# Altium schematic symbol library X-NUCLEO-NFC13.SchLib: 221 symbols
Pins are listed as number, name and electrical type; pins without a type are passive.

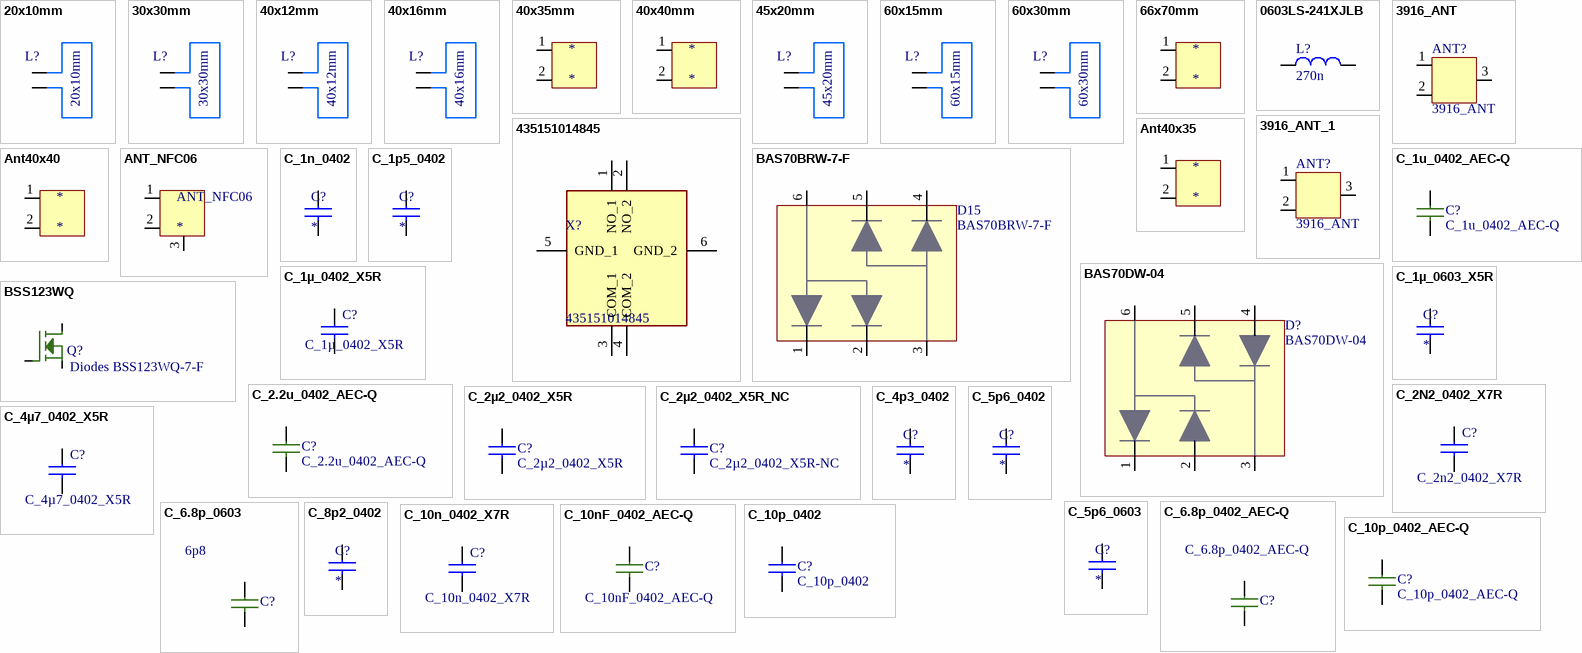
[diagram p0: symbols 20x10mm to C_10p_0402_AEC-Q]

## 20x10mm
designator L?, comment Loop Antenna  (value not drawn)
3turns; 0.2mm width; 0.2mm gap
footprint 20x10mm (3turns; 0.2mm width; 0.2mm gap)
pins: 1, 2

## 30x30mm
designator L?, comment Loop Antenna  (value not drawn)
3turns; 0.3mm width; 0.15mm gap
footprint 30x30mm (2turns; 0.3mm width; 0.15mm gap)
pins: 1, 2

## 40x12mm
designator L?, comment Loop Antenna  (value not drawn)
3turns; 0.3mm width; 0.15mm gap
footprint 40x12mm (3turns; 0.3mm width; 0.15mm gap)
pins: 1, 2

## 40x16mm
designator L?, comment Loop Antenna  (value not drawn)
3turns; 0.3mm width; 0.15mm gap
footprint 40x16mm (3turns; 0.3mm width; 0.15mm gap)
pins: 1, 2

## 40x35mm
designator *  (net tie, no BOM)
4turns;
footprint ANT40x35 (40mm times 35mm)
pins: 1, 2, 3 hidden

## 40x40mm
designator *  (net tie, no BOM)
4turns;
footprint ANT40x40 (40mm times 40mm)
pins: 1, 2, 3 hidden

## 45x20mm
designator L?, comment Loop Antenna  (value not drawn)
3turns; 0.3mm width; 0.15mm gap
footprint 45x20mm (2turns; 0.3mm width; 0.15mm gap)
pins: 1, 2

## 60x15mm
designator L?, comment Loop Antenna  (value not drawn)
3turns; 0.3mm width; 0.15mm gap
footprint 60x15mm (2turns; 0.3mm width; 0.15mm gap)
pins: 1, 2

## 60x30mm
designator L?, comment Loop Antenna  (value not drawn)
2turns; 0.3mm width; 0.15mm gap
footprint 60x30mm (2turns; 0.3mm width; 0.15mm gap)
pins: 1, 2

## 66x70mm
designator *  (net tie, no BOM)
2turns
footprint ST25R_3916DB_66x66mm (66mm x 66mm)
pins: 1, 2

## 0603LS-241XJLB
designator L?, comment 270n
MLJ1608WR27JT000; Manufacturer: TDK; 2nd Source: 0.27 uH 5 % 0.55A 0603
footprint L0603
pins: 1, 2

## 3916_ANT
designator ANT?  (net tie, no BOM)
ST25R3916 DB Ant
footprint ST25R_3916DB__ANTM_42x48mm (42mm x 48mm)
footprint ST25R_3916DB__ANTL_66x66mm (66mm x 66mm)
pins: 1, 2, 3

## 3916_ANT_1
designator ANT?, comment 3916_ANT  (net tie, no BOM)
ST25R300
footprint ST25R300_ANTL_66X66MM (66mm x 66mm)
pins: 1, 2, 3

## 435151014845
designator X?
Tactile Switches WS-TASV Tact Switch; Manufacturer_Name: Wurth Elektronik; Geometry.Height: 1.4mm
footprint 435151014845
pins: 1 NO_1, 2 NO_2, 3 COM_1, 4 COM_2, 5 GND_1, 6 GND_2

## Ant40x35
designator *  (net tie, no BOM)
footprint ANT40x35 (40mm times 35mm)
pins: 1, 2, 3 hidden

## Ant40x40
designator *  (net tie, no BOM)
footprint ANT40x40 (40mm times 40mm)
pins: 1, 2, 3 hidden

## ANT_NFC06
designator ANT_NFC06  (net tie, no BOM)
ANT_NFC06
footprint ANT_NFC08 (40mm times 35mm)
pins: 1, 2, 3

## BAS70BRW-7-F
designator D15
Schottky Diodes & Rectifiers 200MW 70V BRIDGE; Manufacturer: Micro Commercial Components (MCC)
footprint BAS70BRW (SOT363)
pins: 1, 2, 3, 4, 5, 6

## BAS70DW-04
designator D?
Schottky Diodes & Rectifiers 200MW 70V BRIDGE; Manufacturer: Micro Commercial Components (MCC)
footprint BAS70BRW (SOT363)
pins: 1, 2, 3, 4, 5, 6

## BSS123WQ
designator Q?, comment Diodes BSS123WQ-7-F
nCh MOS Fet; Manufacturer: Diodes Incorporated; 2nd Source: no
footprint SOT323
pins: 1 G, 2 S, 3 D

## C_1n_0402
designator C?
1n_COG; Manufacturer: MURATA; Manufacturer Part Number: GRM1555C1H102GA01D; 2nd Source: 1nF ±2% 50V  C0G, NP0 0402
footprint C0402
pins: 1, 2

## C_1p5_0402
designator C?
1p5_COG; Manufacturer: MURATA; Manufacturer Part Number: GRM1555C1H1R5CA01J; 2nd Source: 1,5pF ±0,25pF 50V  C0G, NP0 0603
footprint C0603
pins: 1, 2

## C_1u_0402_AEC-Q
designator C?
1u_X7s; Manufacturer: Murata; Manufacturer Part Number: GRT155R70J105KE01D; 2nd Source: AEC-Q200 10uF ±10% 6.3V 0402
footprint C0402
pins: 1, 2

## C_1µ_0402_X5R
designator C?
1u_X5R; Manufacturer: MURATA; Manufacturer Part Number: GRM155R61C105KA12D; 2nd Source: 0402, 1 µF, 16 V, ± 10%, X5R,
footprint C0402
pins: 1, 2

## C_1µ_0603_X5R
designator C?
1u_X5R; Manufacturer: MURATA; Manufacturer Part Number: GRM188R61C105KA93D; 2nd Source: 0402, 1 µF, 16 V, ± 10%, X5R
footprint C0603
pins: 1, 2

## C_2.2u_0402_AEC-Q
designator C?
2.2u_X7s; Manufacturer: Murata; Manufacturer Part Number: GRT155C70J225KE13; 2nd Source: AEC-Q200 2.2uF ±10% 6.3V 0402
footprint C0402
pins: 1, 2

## C_2N2_0402_X7R
designator C?, comment C_2n2_0402_X7R
2N2_x7R; Manufacturer: AVX; Manufacturer Part Number: 04023C222KAT2A; 2nd Source: 0402, 2.2 nF, 25 V, ± 10%, X7R
footprint C0402
pins: 1, 2

## C_2µ2_0402_X5R
designator C?
2u2_X5R; Manufacturer: MURATA; Manufacturer Part Number: GRM155R60J225ME01D; 2nd Source: 0402, 2.2 µF, 6.3 V, ± 20%, X5R
footprint C0402
pins: 1, 2

## C_2µ2_0402_X5R_NC
designator C?, comment C_2µ2_0402_X5R-NC
2u2_X5R NC; Manufacturer: MURATA; Manufacturer Part Number: GRM155R60J225ME15D NOT FITTED; 2nd Source: 0402, 2.2 µF, 6.3 V, ± 20%, X5R
footprint C0402
pins: 1, 2

## C_4p3_0402
designator C?
4p3_COG; Manufacturer: MURATA; Manufacturer Part Number: GRM0225C1E4R3BA03L; 2nd Source: 0402, 4.3PF 25V, C0G, 0.1pF
footprint C0402
pins: 1, 2

## C_4µ7_0402_X5R
designator C?
4u7_X5R; Manufacturer: TDK; Manufacturer Part Number: C1005X5R0J475K050BC; 2nd Source: 0402, 4.7 µF, 6.3 V, ± 10%, X5R
footprint C0402
pins: 1, 2

## C_5p6_0402
designator C?
5p6_COG; Manufacturer: MURATA; Manufacturer Part Number: GRM1555C1H5R6DA01D; 2nd Source: 5,6pF ±0,5pF 50V  C0G, NP0 0402
footprint C0402
pins: 1, 2

## C_5p6_0603
designator C?
5p6_COG; Manufacturer: MURATA; Manufacturer Part Number: GRM1885C1H5R6CA01D; 2nd Source: 5,6pF ±0,5pF 50V  C0G, NP0 0603
footprint C0603
pins: 1, 2

## C_6.8p_0402_AEC-Q
designator C?
6.8p_COG; Manufacturer: Murta; Manufacturer Part Number: GCM1555C1H6R8BA16D; 2nd Source: AEC-Q200 6.8pF ±0.1pF 100V  C0G 0402
footprint C0402
pins: 1, 2

## C_6.8p_0603
designator C?, comment 6p8
6.8p_COG; Manufacturer: KEMET; Manufacturer Part Number: C0603C689J5GACTU; 2nd Source: 6.8pF 50V  C0G 0603
footprint C0603
pins: 1, 2

## C_8p2_0402
designator C?
8p2_COG; Manufacturer: MURATA; Manufacturer Part Number: GRM1555C1H8R2CA01D; 2nd Source: 0402, 8.2 pF, 50 V, ± 0.25pF, C0G / NP0
footprint C0402
pins: 1, 2

## C_10n_0402_X7R
designator C?
10n_x7R; Manufacturer: AVX; Manufacturer Part Number: 04023C103KAT2A; 2nd Source: 0402, 0.01 µF, 25 V, ± 10%, X7R
footprint C0402
pins: 1, 2

## C_10nF_0402_AEC-Q
designator C?
10n_X7s; Manufacturer: Murata; Manufacturer Part Number: GCM155R71H103KA55J; 2nd Source: AEC-Q200 10nF ±10% 50V 0402
footprint C0402
pins: 1, 2

## C_10p_0402
designator C?
10p_COG; Manufacturer: MURATA; Manufacturer Part Number: GRM1555C1H100GA01D; 2nd Source: 10pF ±2% 50V  C0G, NP0 0402
footprint C0402
pins: 1, 2

## C_10p_0402_AEC-Q
designator C?
10p_COG; Manufacturer: Murta; Manufacturer Part Number: GCM1555C1H100FA16D; 2nd Source: AEC-Q200 10pF ±1% 100V  C0G 0402
footprint C0402
pins: 1, 2

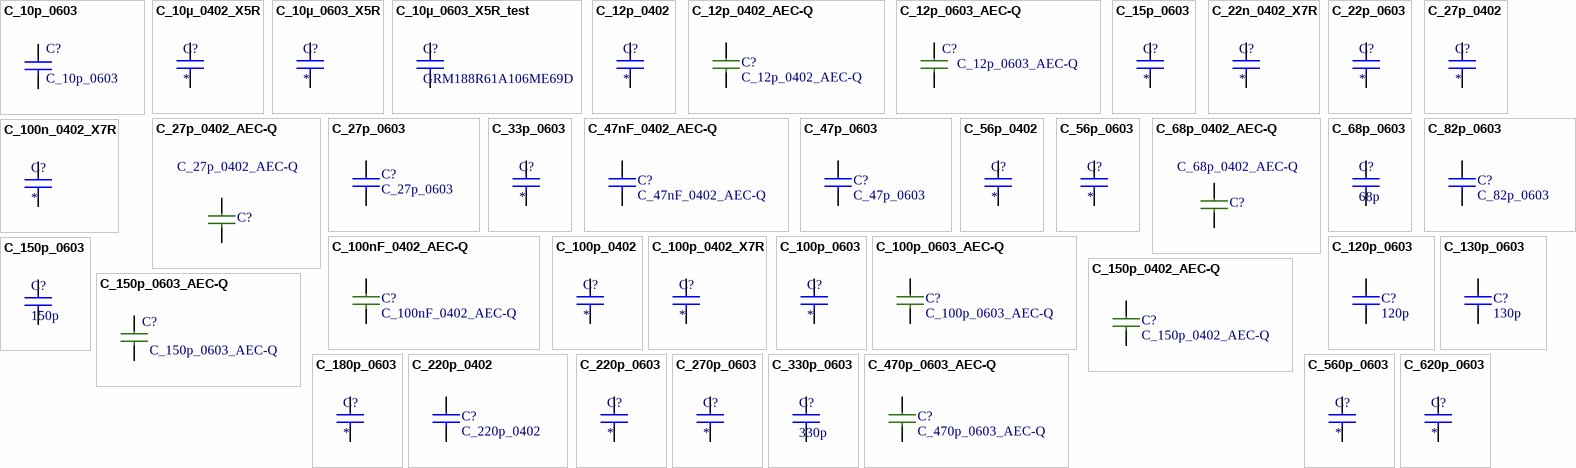
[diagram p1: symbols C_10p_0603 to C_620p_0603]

## C_10p_0603
designator C?
10p_COG; Manufacturer: MULTICOMP; Manufacturer Part Number: MC0603N100F500CT; 2nd Source: 0603, 10pF, 50 V, 1%, C0G / NP0
footprint C0603
pins: 1, 2

## C_10µ_0402_X5R
designator C?
10u_X5R; Manufacturer: muRata; Manufacturer Part Number: GRM155R60G106ME44; 2nd Source: 0402, 10 µF, 6.3 V, ± 10%, X5R
footprint C0402
pins: 1, 2

## C_10µ_0603_X5R
designator C?
10u_X5R; Manufacturer: AVX; Manufacturer Part Number: 06036D106MAT2A; 2nd Source: 0603, 10 µF, 6.3 V, ± 20%, X5R
footprint C0603
pins: 1, 2

## C_10µ_0603_X5R_test
designator C?, comment GRM188R61A106ME69D
10u_X5R
footprint C0603
pins: 1, 2

## C_12p_0402
designator C?
12p_COG; Manufacturer: MURATA; Manufacturer Part Number: GRM1555C1H120GA01D; 2nd Source: 12pF ±2% 50V  C0G, NP0 0402
footprint C0402
pins: 1, 2

## C_12p_0402_AEC-Q
designator C?
12p_COG; Manufacturer: Murta; Manufacturer Part Number: GCM1555C1H120FA16D; 2nd Source: AEC-Q200 12pF ±1% 100V  C0G 0402
footprint C0402
pins: 1, 2

## C_12p_0603_AEC-Q
designator C?
12p_COG; Manufacturer: Murta; Manufacturer Part Number: GCM1885C2A120FA16D; 2nd Source: AEC-Q200 12pF ±1% 100V  C0G 0603
footprint C0603
pins: 1, 2

## C_15p_0603
designator C?
15p_COG; Manufacturer: MULTICOMP; Manufacturer Part Number: MC0603N150J500CT; 2nd Source: 0603, 15pF, 50 V, 1%, C0G / NP0
footprint C0603
pins: 1, 2

## C_22n_0402_X7R
designator C?
22n_x7R; Manufacturer: Murata; Manufacturer Part Number: GRM155R71E223KA61D; 2nd Source: 0402, 0.022 µF, 25 V, ± 10%, X7R
footprint C0402
pins: 1, 2

## C_22p_0603
designator C?
22p_COG; Manufacturer: MURATA; Manufacturer Part Number: GRM1885C1H220FA01D; 2nd Source: 22pF ±2% 50V  C0G, NP0 0603
footprint C0603
pins: 1, 2

## C_27p_0402
designator C?
27p_COG; Manufacturer: MURATA; Manufacturer Part Number: GRM1555C1H270GA01D; 2nd Source: 27pF ±2% 50V  C0G, NP0 0402
footprint C0402
pins: 1, 2

## C_27p_0402_AEC-Q
designator C?
27p_COG; Manufacturer: Murta; Manufacturer Part Number: GCM1555C1H270FA16D; 2nd Source: AEC-Q200 27pF ±1% 100V  C0G 0402
footprint C0402
pins: 1, 2

## C_27p_0603
designator C?
27p_COG; Manufacturer: MURATA; Manufacturer Part Number: GRM1885C1H270FA01D; 2nd Source: 27pF ±2% 50V  C0G, NP0 0603
footprint C0603
pins: 1, 2

## C_33p_0603
designator C?
33p_COGcc; Manufacturer: MURATA; Manufacturer Part Number: GRM1885C1H330FA01D; 2nd Source: 33pF ±2% 50V  C0G, NP0 0603
footprint C0603
pins: 1, 2

## C_47nF_0402_AEC-Q
designator C?
47n_X7s; Manufacturer: Murata; Manufacturer Part Number: GCM155R71E473KA55D; 2nd Source: AEC-Q200 47nF ±10% 10V 0402
footprint C0402
pins: 1, 2

## C_47p_0603
designator C?
47p_COG; Manufacturer: MURATA; Manufacturer Part Number: GRM1885C1H470FA01D; 2nd Source: 47pF ±2% 50V  C0G, NP0 0603
footprint C0603
pins: 1, 2

## C_56p_0402
designator C?
56p_COG; Manufacturer: MURATA; Manufacturer Part Number: GRM1555C1H221GA01D; 2nd Source: 56pF ±2% 50V  C0G, NP0 0402
footprint C0402
pins: 1, 2

## C_56p_0603
designator C?
56p_COG; Manufacturer: MURATA; Manufacturer Part Number: GRM1885C1H560FA01D; 2nd Source: 56pF ±2% 50V  C0G, NP0 0603
footprint C0603
pins: 1, 2

## C_68p_0402_AEC-Q
designator C?
68p_COG; Manufacturer: Murata; Manufacturer Part Number: GCM1555C1H680FA16J; 2nd Source: AEC-Q200 68pF ±1% 50V  C0G 0402
footprint C0402
pins: 1, 2

## C_68p_0603
designator C?, comment 68p
68p_COG; Manufacturer: KEMET; Manufacturer Part Number: C0603C680F1GACTU; 2nd Source: 68pF ±1% 100V  C0G, NP0 0603
footprint C0603
pins: 1, 2

## C_82p_0603
designator C?
82p_COG; Manufacturer: MURATA; Manufacturer Part Number: GRM1885C1H820FA01D; 2nd Source: 82pF ±2% 50V  C0G, NP0 0603
footprint C0603
pins: 1, 2

## C_100n_0402_X7R
designator C?
100n_X7R; Manufacturer: MULTICOMP; Manufacturer Part Number: MC0402X104K100CT; 2nd Source: 0402, 0.1 µF, 10 V, ± 10%, X5R,
footprint C0402
pins: 1, 2

## C_100nF_0402_AEC-Q
designator C?
100n_X7s; Manufacturer: Murata; Manufacturer Part Number: GCM155R71H104KE02J; 2nd Source: AEC-Q200 100nF ±10% 50V 0402
footprint C0402
pins: 1, 2

## C_100p_0402
designator C?
100p_COG; Manufacturer: MURATA; Manufacturer Part Number: GRM1555C1H101GA01D; 2nd Source: 100pF ±2% 50V  C0G, NP0 0402
footprint C0402
pins: 1, 2

## C_100p_0402_X7R
designator C?
100p_X7R; Manufacturer: AVX; Manufacturer Part Number: 0402YC101KAT2A; 2nd Source: 0402, 0.01 µF, 25 V, ± 10%, X7R
footprint C0402
pins: 1, 2

## C_100p_0603
designator C?
100p_COG; Manufacturer: MURATA; Manufacturer Part Number: GRM1885C1H101FA01D; 2nd Source: 100pF ±1% 50V  C0G, NP0 0603
footprint C0603
pins: 1, 2

## C_100p_0603_AEC-Q
designator C?
100p_COG; Manufacturer: Murta; Manufacturer Part Number: GCM1885C2A101FA16D; 2nd Source: AEC-Q200 100pF ±1% 100V  C0G 0603
footprint C0603
pins: 1, 2

## C_120p_0603
designator C?, comment 120p
120p_COG; Manufacturer: KEMET; Manufacturer Part Number: C0603C121J1GACTU; 2nd Source: 120pF ±5% 100V  C0G, NP0 0603
footprint C0603
pins: 1, 2

## C_130p_0603
designator C?, comment 130p
130p_COG; Manufacturer: KEMET; Manufacturer Part Number: C0603C131F5GACTU; 2nd Source: 130pF ±1% 50V  C0G, NP0 0603
footprint C0603
pins: 1, 2

## C_150p_0402_AEC-Q
designator C?
150p_COG; Manufacturer: Murta; Manufacturer Part Number: GCM1555C1H151FA16D; 2nd Source: AEC-Q200 150pF ±1% 50V  C0G 0402
footprint C0402
pins: 1, 2

## C_150p_0603
designator C?, comment 150p
150p_COG; Manufacturer: KEMET; Manufacturer Part Number: C0603C151F5GACTU; 2nd Source: 150pF ±1% 50V  C0G, NP0 0603
footprint C0603
pins: 1, 2

## C_150p_0603_AEC-Q
designator C?
150p_COG; Manufacturer: Murta; Manufacturer Part Number: GCM1885C2A151FA16D; 2nd Source: AEC-Q200 150pF ±1% 100V  C0G 0603
footprint C0603
pins: 1, 2

## C_180p_0603
designator C?
180p_COG; Manufacturer: MURATA; Manufacturer Part Number: GRM1885C1H181GA01D; 2nd Source: 180pF ±2% 50V  C0G, NP0 0603
footprint C0603
pins: 1, 2

## C_220p_0402
designator C?
220p_COG; Manufacturer: MURATA; Manufacturer Part Number: GRM1885C1H221FA01D; 2nd Source: 220pF ±2% 50V  C0G, NP0 0402
footprint C0402
pins: 1, 2

## C_220p_0603
designator C?
220p_COG; Manufacturer: MURATA; Manufacturer Part Number: GRM033R71H221KA12D; 2nd Source: 220pF ±2% 50V  C0G, NP0 0603
footprint C0603
pins: 1, 2

## C_270p_0603
designator C?
270p_COG; Manufacturer: MURATA; Manufacturer Part Number: GRM1885C1H271FA01D; 2nd Source: 270pF ±2% 50V  C0G, NP0 0603
footprint C0603
pins: 1, 2

## C_330p_0603
designator C?, comment 330p
330p_COG; Manufacturer: YAGEO; Manufacturer Part Number: CC0603FRNPO9BN331; 2nd Source: 330pF ±1% 50V  C0G, NP0 0603
footprint C0603
pins: 1, 2

## C_470p_0603_AEC-Q
designator C?
470p_COG; Manufacturer: Murta; Manufacturer Part Number: GCM1885C2A471FA16D; 2nd Source: AEC-Q200 470pF ±1% 100V  C0G 0603
footprint C0603
pins: 1, 2

## C_560p_0603
designator C?
560p_COG; Manufacturer: KEMET; Manufacturer Part Number: C0603C561J3GACTU; 2nd Source: 560pF ±5% 25V  C0G, NP0 0603
footprint C0603
pins: 1, 2

## C_620p_0603
designator C?
620p_COG; Manufacturer: MURATA; Manufacturer Part Number: GCM1885C2A621FA16J; 2nd Source: 620pF ±2% 50V  C0G, NP0 0603
footprint C0603
pins: 1, 2

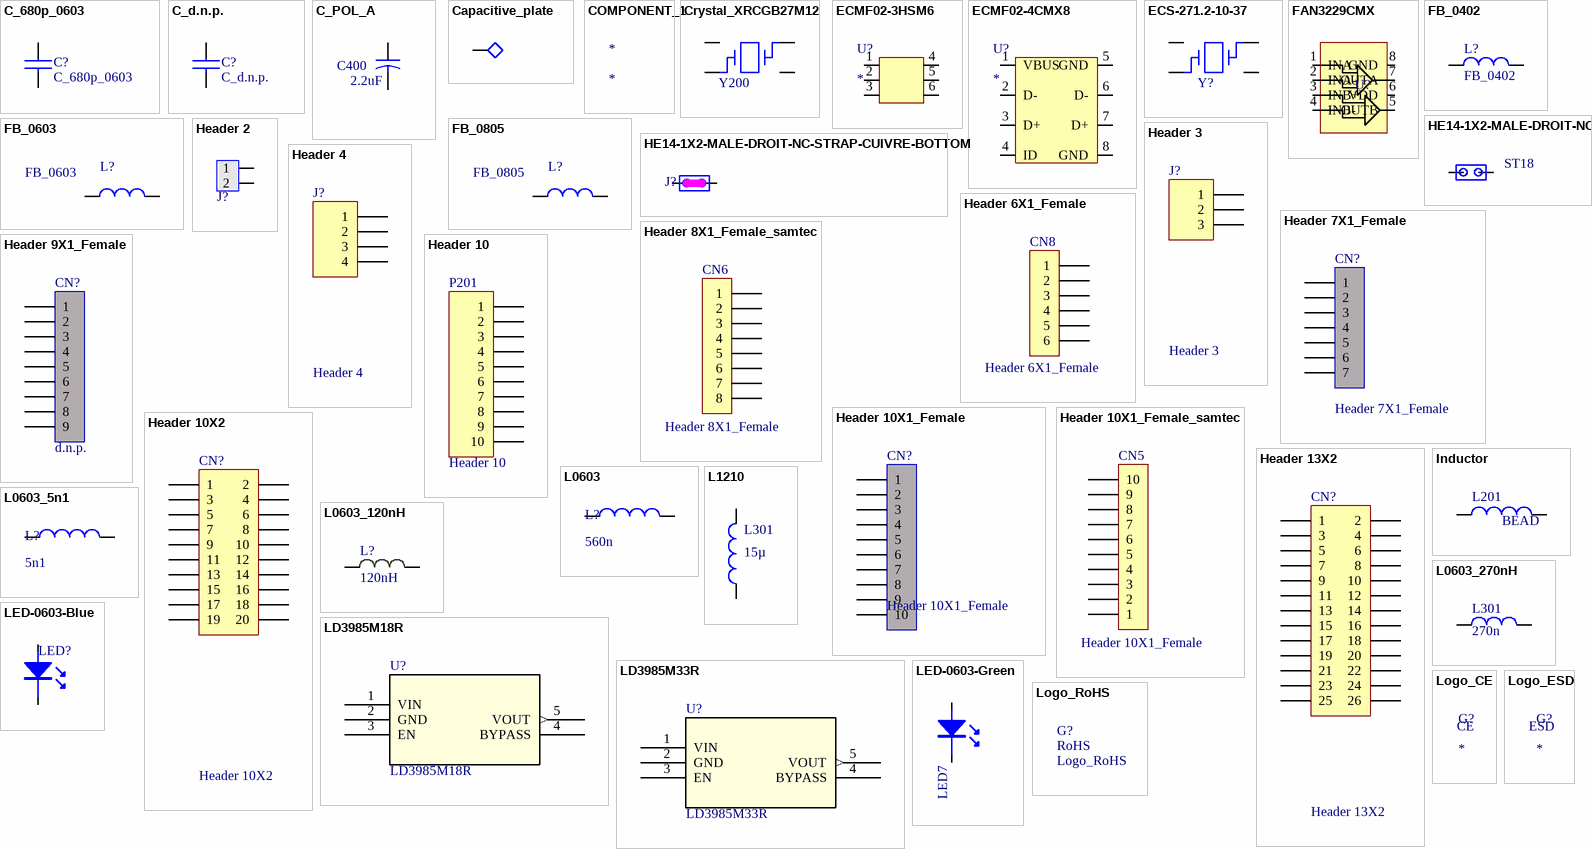
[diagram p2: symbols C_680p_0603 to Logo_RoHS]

## C_680p_0603
designator C?
680p_COG; Manufacturer: MURATA; Manufacturer Part Number: GRM1885C1H681GA01D; 2nd Source: 680pF ±2% 50V  C0G, NP0 0603
footprint C0603
pins: 1, 2

## C_d.n.p.
designator C?
d.n.p.
footprint C0603
footprint C0402
pins: 1, 2

## C_POL_A
designator C400, comment 2.2uF
Manufacturer: Kyocera / AVX; Manufacturer Part Number: TAJA225K010RNJ; Capacitance: 2.2; Voltage Rating: 10; ESR: 7
footprint CP_SMD_A
pins: 1, 2

## Capacitive_plate
designator CP?, comment CS1  (value not drawn)  (no BOM)
Capacitive Sensing
footprint Capacitive_plate
pins: 1

## COMPONENT_1
designator *

## Crystal_XRCGB27M12
designator Y200, comment 27,12MHz Crystal  (value not drawn)
Manufacturer: MURATA; Manufacturer Part Number: XRCGB27M120F3M00R0
footprint XRCGB_F_MN
pins: 1, 2, 3, 4

## ECMF02-3HSM6
designator U?
ECMF02-3HSM6
footprint uQFN-6L (ECMF02-3HSM6)
pins: 1, 2, 3, 4, 5, 6

## ECMF02-4CMX8
designator U?
ECMF02-4CMX8; Manufacturer: STMicroelectronics
footprint uQFN-8L (ECMF02-4CMX8)
pins: 1 VBUS, 2 D-, 3 D+, 4 ID, 5 GND, 6 D-, 7 D+, 8 GND

## ECS-271.2-10-37
designator Y?, comment ECS 27,12MHz Crystal  (value not drawn)
CRYSTAL 27.1200MHZ 10PF SMD; Manufacturer Part Number: ECS-271.2-10-37-CKM-TR
footprint XRCGB_F_MN
pins: 1, 2, 3, 4

## FAN3229CMX
designator U?  (value not drawn)
nCh MOS Fet; Manufacturer: onsemi; 2nd Source: no
footprint FAN3229t (SOIC, 8-Leads, Body 4,90x3,90mm, Pitch 1,27mm, IPC Medium Density)
pins: 1 INA+ (in), 2 INA- (in), 3 INB+ (in), 4 INB- (in), 5 OUTB (out), 6 VDD (power), 7 OUTA (out), 8 GND (power)

## FB_0402
designator L?
Manufacturer: muRata; Manufacturer Part Number: BLM15EG121SH1D; 2nd Source: No
footprint L0402
pins: 1, 2

## FB_0603
designator L?
Manufacturer: MURATA; Manufacturer Part Number: BLM18EG471SN1D
footprint L0603
pins: 1, 2

## FB_0805
designator L?
Manufacturer: TAIYO YUDEN; Manufacturer Part Number: BK2125HS470-T
footprint L0805
pins: 1, 2

## HE14-1X2-MALE-DROIT-NC
designator ST18, comment HE14 2PTS NC  (value not drawn)
CONN HE14 2PTS MALE VERTICAL NOT FITTED; 2nd Source: doublesourcing allowed; PickPlace: No
footprint HE14-1x2-DROIT
pins: 1, 2

## HE14-1X2-MALE-DROIT-NC-STRAP-CUIVRE-BOTTOM
designator J?, comment HE14 2PTS  (value not drawn)  (net tie)
CONN HE14 2PTS MALE VERTICAL NOT FITTED; 2nd Source: doublesourcing allowed
footprint HE14-1x2-DROIT-AVEC-STRAP-CUIVRE-BOTTOM
pins: 1, 2

## Header 2
designator J?, comment d.n.p.  (value not drawn)  (no BOM)
Male Single Row Horizontal 2 pin; 2nd Source: doublesourcing allowed
footprint HDR1X2_slim (Connector; Header; 2 Position)
pins: 1, 2

## Header 3
designator J?
Samtec; Manufacturer Part Number: FTS-103-01-L-S
footprint Header 3X (3 Pin header)
pins: 1, 2, 3

## Header 4
designator J?
Samtec; Manufacturer Part Number: FTS-104-01-L-S
footprint Header 4X (4 Pin header)
pins: 1, 2, 3, 4

## Header 6X1_Female
designator CN8
Header, 6-Pin, Single row,female; Manufacturer: Samtec; Manufacturer Part Number: SSQ-106-03-L-S; Comments: RECEPTACLE, 2.54MM, SINGLE ROW, 6 WAY; 2nd source: doublesourcing allowed; PickPlace: No
footprint SAMTEC-SSQ-1x6-DROIT-STYLE-03
pins: 1, 2, 3, 4, 5, 6

## Header 7X1_Female
designator CN?
d.n.p.; Manufacturer: Samtec; Manufacturer Part Number: SSQ-107-03-L-S; Comments: RECEPTACLE, 2.54MM, SINGLE ROW, 7WAY; 2nd source: doublesourcing allowed
pins: 1, 2, 3, 4, 5, 6, 7

## Header 8X1_Female_samtec
designator CN6, comment Header 8X1_Female
Header, 8-Pin, Single row,female; Manufacturer: Samtec; Manufacturer Part Number: SSQ-108-03-L-S; Comments: RECEPTACLE, 2.54MM, SINGLE ROW, 8WAY; 2nd source: doublesourcing allowed; PickPlace: No
footprint SAMTEC-SSQ-1x8-DROIT-STYLE-03
pins: 1, 2, 3, 4, 5, 6, 7, 8

## Header 9X1_Female
designator CN?, comment d.n.p.  (no BOM)
Manufacturer: Samtec; Manufacturer Part Number: SSQ-107-03-L-S; Comments: RECEPTACLE, 2.54MM, SINGLE ROW, 7WAY; 2nd source: doublesourcing allowed
footprint 1*9P_MALE
pins: 1, 2, 3, 4, 5, 6, 7, 8, 9

## Header 10
designator P201
Samtec; Manufacturer Part Number: FTS-105-01-L-DV
footprint Samtec-Strip5x2
pins: 1, 2, 3, 4, 5, 6, 7, 8, 9, 10

## Header 10X1_Female
designator CN?
TSW-110-08-G-S-RA; Manufacturer: Samtec; Comments: RECEPTACLE, 2.54MM, SINGLE ROW, 7WAY; 2nd source: doublesourcing allowed
pins: 1, 2, 3, 4, 5, 6, 7, 8, 9, 10

## Header 10X1_Female_samtec
designator CN5, comment Header 10X1_Female
Header, 10-Pin, Single row,female; Manufacturer: Samtec; Manufacturer Part Number: SSQ-110-03-L-S; Comments: RECEPTACLE, 2.54MM, SINGLE ROW, 10WAY; 2nd source: doublesourcing allowed; PickPlace: No
footprint SAMTEC-SSQ-1x10-DROIT-STYLE-03
pins: 1, 2, 3, 4, 5, 6, 7, 8, 9, 10

## Header 10X2
designator CN?
Header, 10-Pin, Dual row; Manufacturer: Samtec; Manufacturer Part Number: CES-119-01-T-D; 2nd Source: doublesourcing allowed
signal-integrity model Connector
footprint 2*13P
pins: 1, 2, 3, 4, 5, 6, 7, 8, 9, 10, 11, 12, 13, 14, 15, 16, 17, 18, 19, 20

## Header 13X2
designator CN?
Header, 13-Pin, Dual row; Manufacturer: Würth Elektronik; Manufacturer Part Number: 61202621621; 2nd Source: doublesourcing allowed
signal-integrity model Connector
footprint 2*13P
pins: 1, 2, 3, 4, 5, 6, 7, 8, 9, 10, 11, 12, 13, 14, 15, 16, 17, 18, 19, 20, 21, 22, 23, 24, 25, 26

## Inductor
designator L201, comment BEAD
Inductor
footprint L0603
pins: 1, 2

## L0603
designator L?, comment 560n
COILCRAFT   0603LS-561XGLB   Surface Mount High Frequency Inductor, 0603LS Series, 560 nH,  2%, 0603 [1608 Metric], 525 MHz; Manufacturer Part Number: 0603LS-561XJRC; 2nd Source: No
footprint L0603
pins: 1, 2

## L0603_5n1
designator L?, comment 5n1
COILCRAFT   0603CS-5N1EGTS  Surface Mount High Frequency Inductor, 0603CS Series, 5.1nH,  2%, 0603; Manufacturer Part Number: 0603CS-5N1XJLU; 2nd Source: no; Core Material: Ferrite,Ceramic; Self Resonant Frequency: 525MHz; Inductance: 560nH; Max DC Current: 550mA; DC Resistance (DCR): 440mR; Test Frequency: 7.9MHz; Q Factor: 15
footprint L0603
pins: 1, 2

## L0603_120nH
designator L?, comment 120nH
LQW18CNR27J0ZD; Manufacturer: Murata; Manufacturer Part Number: LQW18CNR12J0ZD; 2nd Source: no
footprint L0603
pins: 1, 2

## L0603_270nH
designator L301, comment 270n
0603LS-271XGRC; Manufacturer: CoilCraft; 2nd Source: no
footprint L0603
pins: 1, 2

## L1210
designator L301, comment 15µ
FIXED IND 15UH 300MA 650 MOHM; Manufacturer: Murata; Manufacturer Part Number: LQH32DN150K53L; 2nd Source: no
footprint L1210
pins: 1, 2

## LD3985M18R
designator U?
1.8V LDO; Manufacturer: STMicroelectronics; 2nd Source: no
footprint LD3985 (SOT23, 5-Leads, Body 2,90x2,80mm, Pitch 0,95mm, IPC Medium Density)
pins: 1 VIN, 2 GND, 3 EN, 4 BYPASS, 5 VOUT (out)

## LD3985M33R
designator U?
3.3V LDO; Manufacturer: STMicroelectronics; 2nd Source: no
footprint LD3985 (SOT23, 5-Leads, Body 2,90x2,80mm, Pitch 0,95mm, IPC Medium Density)
pins: 1 VIN, 2 GND, 3 EN, 4 BYPASS, 5 VOUT (out)

## LED-0603-Blue
designator LED?, comment Blue  (value not drawn)
Manufacturer: Lite-On; Manufacturer Part Number: LTST-C190TBKT
footprint D0603
pins: 1, 2

## LED-0603-Green
designator LED7, comment Green  (value not drawn)
Manufacturer: Lite-On; Manufacturer Part Number: LTST-C190KGKT; PickPlace: Yes
footprint D0603
pins: 1, 2

## Logo_CE
designator G?
footprint Logo_CE (Silk only)

## Logo_ESD
designator G?
footprint Logo_ESD (Silk only)

## Logo_RoHS
designator G?
footprint Logo_RoHS_CHN (Silk only)

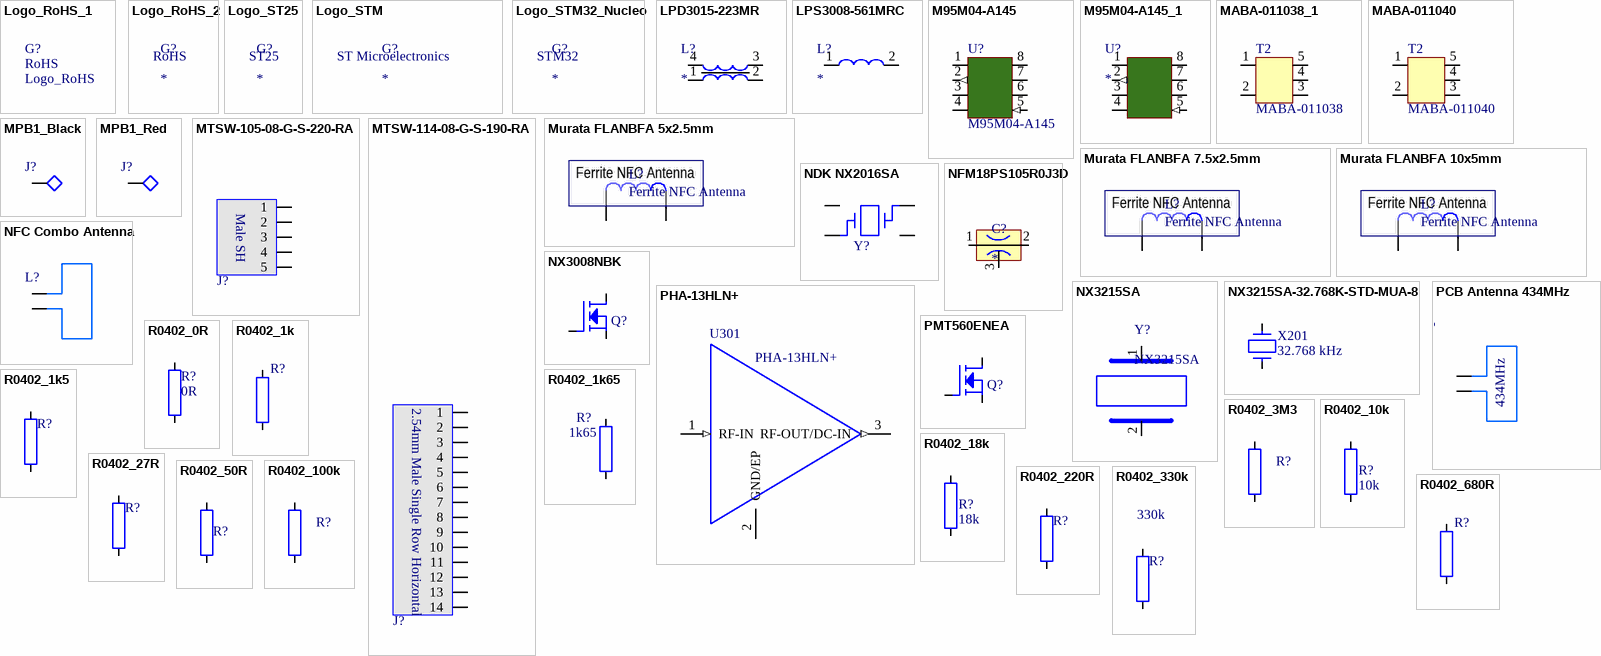
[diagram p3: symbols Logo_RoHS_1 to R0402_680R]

## Logo_RoHS_1
designator G?, comment Logo_RoHS
footprint Logo_RoHS_CHN (Silk only)

## Logo_RoHS_2
designator G?
footprint Logo_RoHS (Silk only)

## Logo_ST25
designator G?
footprint Logo_ST25 (Silk Only)

## Logo_STM
designator G?
footprint Logo_STM (Silk olnly)

## Logo_STM32_Nucleo
designator G?
footprint Logo_STM32 (silk only)

## LPD3015-223MR
designator L?
footprint LPD3015 (LPD3015-223MR_)
pins: 1, 2, 3, 4

## LPS3008-561MRC
designator L?
Manufacturer: CoilCraft; Manufacturer Part Number: LPS3008-561MRC
footprint LPS3008-561MR_
pins: 1, 2

## M95M04-A145
designator U?
footprint TSOP65P640X120-8N (TSOP, 8-Leads, Body 3,00x4,40mm, Pitch 0,65mm, IPC Medium Density)
pins: 1 /CS, 2 MISO (out), 3 /HOLD, 4 VSS (power), 5 MOSI (in), 6, 7 SCLK, 8 VCC (power)

## M95M04-A145_1
designator U?
M95M04-A145
footprint TSOP65P640X120-8N (TSOP, 8-Leads, Body 3,00x4,40mm, Pitch 0,65mm, IPC Medium Density)
pins: 1 /CS, 2 MISO (out), 3 /HOLD, 4 VSS (power), 5 MOSI (in), 6, 7 SCLK, 8 VCC (power)

## MABA-011038_1
designator T2, comment MABA-011038
Manufacturer: MACOM; 2nd Source: no
footprint MABA-011038
pins: 1, 2, 3, 4, 5

## MABA-011040
designator T2
Manufacturer: MACOM; 2nd Source: no
footprint MABA-011038
pins: 1, 2, 3, 4, 5

## MPB1_Black
designator J?, comment MPB1  (value not drawn)
Black MPB1 Power Plug; Manufacturer: HIRSCHMANN TEST AND MEASUREMENT; Manufacturer Part Number: 930224100; 2nd Source: yes
footprint PowerPlug_MPB1SW (Connector; Header; 2 Position)
pins: 1

## MPB1_Red
designator J?, comment MPB1  (value not drawn)
Red MPB1 Power Plug; Manufacturer: HIRSCHMANN TEST AND MEASUREMENT; Manufacturer Part Number: 930224101; 2nd Source: yes
footprint PowerPlug_MPB1R (Connector; Header; 2 Position)
pins: 1

## MTSW-105-08-G-S-220-RA
designator J?, comment Male Single Row Horizontal  (value not drawn)
Headers & Wire Housings Variable Height PCB Header Strips, 0.100" pitch; Manufacturer: Samtec; Manufacturer Part Number: MTSW-105-08-G-S-220-RA; 2nd Source: doublesourcing allowed
footprint MTSW-105-08-G-S-220-RA (5 Pin header 90deg)
pins: 1, 2, 3, 4, 5

## MTSW-114-08-G-S-190-RA
designator J?, comment Male Single Row Horizontal  (value not drawn)
Headers & Wire Housings Variable Height PCB Header Strips, 0.100" pitch; Manufacturer: Samtec; Manufacturer Part Number: MTSW-114-08-G-S-190-RA; 2nd Source: doublesourcing allowed
footprint MTSW-114-08-G-S-190-RA (Footprint not found)
pins: 1, 2, 3, 4, 5, 6, 7, 8, 9, 10, 11, 12, 13, 14

## Murata FLANBFA 5x2.5mm
designator L?, comment Ferrite NFC Antenna
Murata 5x2.5 mm Antenna
footprint FLANBFA 5x2.5MM (Common Footprint for Murata 5 x 2,5 mm Antenna)
pins: 0, 1

## Murata FLANBFA 7.5x2.5mm
designator L?, comment Ferrite NFC Antenna
Murata 7.5x2.5mm Antenna
footprint FLANBFA 7.5x2.5MM (Common Footprint for Murata 7,5 x 2,5 mm Antenna)
pins: 0, 1

## Murata FLANBFA 10x5mm
designator L?, comment Ferrite NFC Antenna
Murata 10x5mm Antenna
footprint FLANBFA 10x5mm (Common Footprint for Murata 10x5 mm Antenna)
pins: 0, 1

## NDK NX2016SA
designator Y?, comment NDK 27,12MHz Crystal  (value not drawn)
NDK NX2016SA 27.12MHz; Manufacturer: MURATA; Manufacturer Part Number: NX2016SA STD-CZS-5 27.12MHz; 2nd Source: Murata XRCGB27M120F3M00R0
footprint XRCGB_F_MN
pins: 1, 2, 3, 4

## NFC Combo Antenna
designator L?, comment Loop Antenna  (value not drawn)
2turns; 0.3mm width; 0.15mm gap
footprint ST25R_3916DB_combo (70mm x 70mm)
pins: 1, 2

## NFM18PS105R0J3D
designator C?
Manufacturer: MURATA; Manufacturer Part Number: NFM18PS105R0J3D
footprint NFM18
pins: 1, 2, 3

## NX3008NBK
designator Q?  (value not drawn)
nCh MOS Fet - NX3008NBK
footprint SOT23
pins: 1 G, 2 S, 3 D

## NX3215SA
designator Y?
32.768kHz; Manufacturer: NDK; Manufacturer Part Number: NX3215SA-32.768K-STD-MUA-8
footprint NX3215SA (NX3215SA-32.768K-STD-MUA-8)
pins: 1, 2

## NX3215SA-32.768K-STD-MUA-8
designator X201, comment 32.768 kHz
Crystal 32kHz; Manufacturer Part Number: NX3215SA-32.768K-STD-MUA-8; Manufacturer: NDK
footprint NX3215SA (NX3215SA-32.768K-STD-MUA-8)
pins: 1, 2
2 alternate drawings of the same symbol

## PCB Antenna 434MHz
designator L?, comment 434MHz PCB Antenna  (net tie, no BOM)
PCB Antenna 434 MHz Reference Design
footprint 434MHz RD PCB Antenna (434MHz Reference PCB Antenna)
pins: 1, 2

## PHA-13HLN+
designator U301
Manufacturer: Mini-Circuits
footprint SOT89-150P410X160-3N (SOT89, 3-Leads, Body 4,49x2,44mm, Pitch 1,50mm, Lead Span 4,1mm, IPC Medium Density)
pins: 1 RF-IN (in), 2 GND/EP, 3 RF-OUT/DC-IN (out)

## PMT560ENEA
designator Q?  (value not drawn)
nCh MOS Fet; Manufacturer Part Number: PMT560ENEAX; Manufacturer: NEXPERIA; 2nd Source: no
footprint SOT23
pins: 1 G, 2 S, 3 D

## R0402_0R
designator R?, comment 0R
0R, 0402; Manufacturer: VISHAY; Manufacturer Part Number: CRCW04020000ZSTD; 2nd Source: 0 ohm, 50 V, 0402, >62.5 mW
footprint R0402
pins: 1, 2

## R0402_1k
designator R?, comment 1k  (value not drawn)
1k, 0402; Manufacturer: Panasonic; Manufacturer Part Number: ERJ2GEJ102X; 2nd Source: 1 kohm, 50 V, 0402, >100 mW, ± 5%
footprint R0402
pins: 1, 2

## R0402_1k5
designator R?, comment 1k5  (value not drawn)
1k5, 0402; Manufacturer: Stackpole Electronics Inc; Manufacturer Part Number: RMCF0402FT1K00; 2nd Source: 1.5 kohm, 50 V, 0402, >100 mW, ± 1%
footprint R0402
pins: 1, 2

## R0402_1k65
designator R?, comment 1k65
1k65, 0402; Manufacturer: MULTICOMP; Manufacturer Part Number: MC00625W040211K65; 2nd Source: 1.65 kohm, 50 V, 0402, >62.5 mW, ± 1%
footprint R0402
pins: 1, 2

## R0402_3M3
designator R?, comment 3M3  (value not drawn)
3M3, 0402; Manufacturer: YAGO; Manufacturer Part Number: RC0402FR-073M3L; 2nd Source: 3.3 Mohm, 50 V, 0402, >62.5 mW, ± 1%
footprint R0402
pins: 1, 2

## R0402_10k
designator R?, comment 10k
10k, 0402; Manufacturer: MULTICOMP; Manufacturer Part Number: MC00625W0402110K; 2nd Source: 10 kohm, 50 V, 0402, >62.5 mW, ± 1%
footprint R0402
pins: 1, 2

## R0402_18k
designator R?, comment 18k
18k, 0402; Manufacturer: MULTICOMP; Manufacturer Part Number: MCWR04X1802FTL; 2nd Source: 18 kohm, 50 V, 0402, >62.5 mW, ± 1%
footprint R0402
pins: 1, 2

## R0402_27R
designator R?, comment 27R  (value not drawn)
27R, 0402; Manufacturer: MULTICOMP; Manufacturer Part Number: MC00625W0402127R; 2nd Source: 27ohm, 50 V, 0402, >62.5 mW, ± 1%
footprint R0402
pins: 1, 2

## R0402_50R
designator R?, comment 50R  (value not drawn)
50R, 0402; Manufacturer: MULTICOMP; Manufacturer Part Number: MCMR04X49R9FTL; 2nd Source: 49.9 ohm, 50 V, 0402, >62.5 mW, ± 1%
footprint R0402
pins: 1, 2

## R0402_100k
designator R?, comment 100k  (value not drawn)
100k, 0402; Manufacturer: YAGO; Manufacturer Part Number: RC0402FR-10100KL; 2nd Source: 100 kohm, 50 V, 0402, >62.5 mW, ± 1%
footprint R0402
pins: 1, 2

## R0402_220R
designator R?, comment 220R  (value not drawn)
220R, 0402; Manufacturer: Yageo; Manufacturer Part Number: RC0402JR-07220RL; 2nd Source: 220 Ohm ±5% 0.063W, 1/16W Chip Resistor 0402
footprint R0402
pins: 1, 2

## R0402_330k
designator R?, comment 330k
330k, 0402; Manufacturer: VISHAY; Manufacturer Part Number: CRCW0402330KFKED; 2nd Source: 330 kohm, 50 V, 0402, >62.5 mW, ± 1%
footprint R0402
pins: 1, 2

## R0402_680R
designator R?, comment 680R  (value not drawn)
680R, 0402; Manufacturer: Yageo; Manufacturer Part Number: RC0402JR-07680RL; 2nd Source: 680 Ohm ±5% 0.063W, 1/16W Chip Resistor 0402
footprint R0402
pins: 1, 2

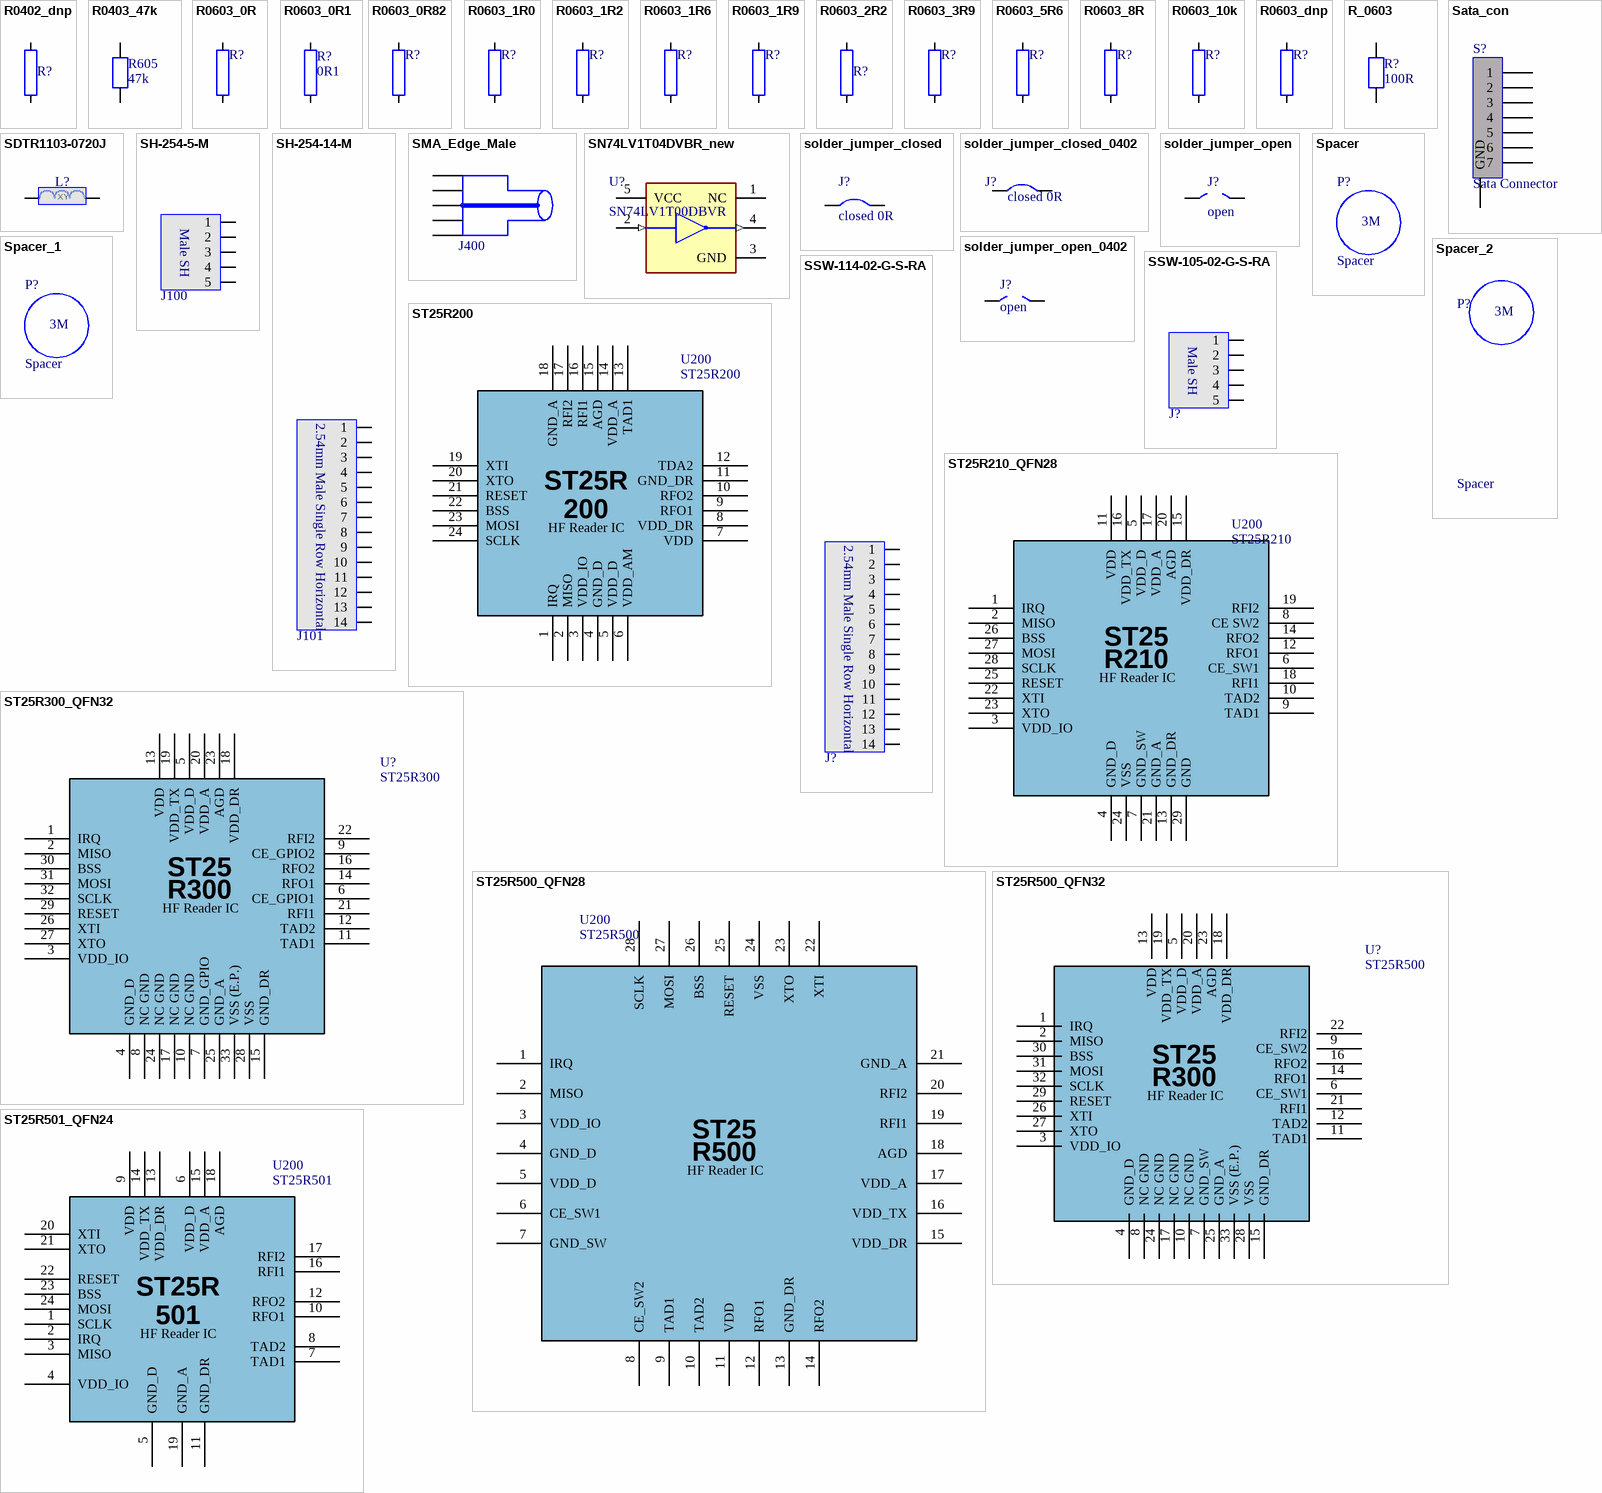
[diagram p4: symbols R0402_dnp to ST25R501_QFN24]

## R0402_dnp
designator R?, comment d.n.p.  (value not drawn)
d.n.p., 0402
footprint R0402
pins: 1, 2

## R0403_47k
designator R605, comment 47k
Manufacturer 1: VISHAY; Manufacturer Part Number: CRCW040247K0FKED; 2nd Source: 47k 0402 1% 62.5mW
footprint R0402
footprint R0603-ss
pins: 1, 2

## R0603_0R
designator R?, comment 0R  (value not drawn)
0R, 0603; Manufacturer: Yageo; Manufacturer Part Number: RC0603FR-070RL; 2nd Source: 0 Ohm ±5% 0.1W, 1/10W Chip Resistor 0603
footprint R0603
pins: 1, 2

## R0603_0R1
designator R?, comment 0R1
0R1, 0603; Manufacturer: MULTICOMP; Manufacturer Part Number: MC00625W040210R; 2nd Source: 0 ohm, 50 V, 0402, >62.5 mW
footprint R0603
pins: 1, 2

## R0603_0R82
designator R?, comment 0R82  (value not drawn)
0R82, 0603; Manufacturer: Panasonic; Manufacturer Part Number: ERJ3BQFR82V; 2nd Source: 0.82 Ohm ±1% 0.33W, 1/3W Chip Resistor 0603
footprint R0603
pins: 1, 2

## R0603_1R0
designator R?, comment 1R0  (value not drawn)
1R0, 0603; Manufacturer: Panasonic; Manufacturer Part Number: ERJ-3RQF1R0V; 2nd Source: 1 Ohm ±1% 0.333W, 1/3W Chip Resistor 0603
footprint R0603
pins: 1, 2

## R0603_1R2
designator R?, comment 1R2  (value not drawn)
1R2, 0603; Manufacturer: Vishay Dale; Manufacturer Part Number: CRCW06031R20FKEA; 2nd Source: 1.2 Ohm ±1% 0.1W, 1/10W Chip Resistor 0603
footprint R0603
pins: 1, 2

## R0603_1R6
designator R?, comment 1R6  (value not drawn)
1R6, 0603; Manufacturer: Vishay Dale; Manufacturer Part Number: CRCW06031R60FKEAHP; 2nd Source: 1.6 Ohm ±1% 0.1W, 1/10W Chip Resistor 0603
footprint R0603
pins: 1, 2

## R0603_1R9
designator R?, comment 1R9  (value not drawn)
1R9, 0603; Manufacturer: Vishay Dale; Manufacturer Part Number: CRCW06031R96FKEA; 2nd Source: 1.96 Ohm ±1% 0.1W, 1/10W Chip Resistor 0603
footprint R0603
pins: 1, 2

## R0603_2R2
designator R?, comment 2R2  (value not drawn)
2R2, 0603; Manufacturer: Vishay Dale; Manufacturer Part Number: CRCW06032R20FKEA; 2nd Source: 2.2 Ohm ±1% 0.1W, 1/10W Chip Resistor 0603
footprint R0603
pins: 1, 2

## R0603_3R9
designator R?, comment 3R9  (value not drawn)
3R9, 0603; Manufacturer: Panasonic; Manufacturer Part Number: ERJ-3GEYJ3R9V; 2nd Source: 3.9 Ohm ±5% 0.1W, 1/10W Chip Resistor 0603
footprint R0603
pins: 1, 2

## R0603_5R6
designator R?, comment 3R9  (value not drawn)
5R6, 0603; Manufacturer: Yageo; Manufacturer Part Number: RC0603FR-075R62L; 2nd Source: 5.6 Ohm ±5% 0.1W, 1/10W Chip Resistor 0603
footprint R0603
pins: 1, 2

## R0603_8R
designator R?, comment 8R  (value not drawn)
8R, 0603; Manufacturer: Yageo; Manufacturer Part Number: 311-18GRTR-ND; 2nd Source: 8 Ohm ±5% 0.1W, 1/10W Chip Resistor 0603
footprint R0603
pins: 1, 2

## R0603_10k
designator R?, comment 10k  (value not drawn)
10k, 0603; Manufacturer: Vishay Dale; Manufacturer Part Number: CRCW060310K0FKTA; 2nd Source: 10 kOhm ±1% 0.1W, 1/10W Chip Resistor 0603
footprint R0603
pins: 1, 2

## R0603_dnp
designator R?, comment dnp  (value not drawn)
dnp, 0603; 2nd Source: d.n.p., 1/10W Chip Resistor 0603
footprint R0603
pins: 1, 2

## R_0603
designator R?, comment 100R
2nd Source: 100R 0402
footprint R0402
footprint R0603-ss
pins: 1, 2

## Sata_con
designator S?, comment Sata Connector
CONN SATA HEADER 7POS SLD PCB; Manufacturer: Molex; Manufacturer Part Number: 0471554001; 2nd source: doublesourcing allowed
footprint Sata Con Molex
pins: 1, 2, 3, 4, 5, 6, 7, 8 GND

## SDTR1103-0720J
designator L?, comment Premo Horizontal Single Axis 125kHz coil  (value not drawn)
footprint SDTR1103 (Premo 125kHz Horizontal Transponder Antenna)
pins: 0, 1

## SH-254-5-M
designator J100, comment Male Single Row Horizontal  (value not drawn)
Male Single Row Horizontal 5 pin; Manufacturer: Samtec; Manufacturer Part Number: TSM-105-01-L-SH; 2nd Source: doublesourcing allowed
footprint Male_SH-254-05 (SMT 2,54mm Single Row Horizontal)
pins: 0 1, 1 2, 2 3, 3 4, 4 5

## SH-254-14-M
designator J101, comment Male Single Row Horizontal  (value not drawn)
Male Single Row Horizontal 14 pin; Manufacturer: Samtec; Manufacturer Part Number: TSM-114-01-L-SH; 2nd Source: doublesourcing allowed
footprint Male_SH-254-14 (SMT 2,54mm Single Row Horizontal)
pins: 0 1, 1 2, 2 3, 3 4, 4 5, 5 6, 6 7, 7 8, 8 9, 9 10, 10 11, 11 12, 12 13, 13 14

## SMA_Edge_Male
designator J400  (value not drawn)
SMA END LAUNCH PLG RCP .062 PC; Manufacturer: Amphenol Connex; Manufacturer Part Number: 132366-10; Body Plating: Gold; Body Material: Brass; Dielectric Material: PTFE; Connector Type: SMA,Receptacle,Male Pin; Max Frequency: 18GHz; Impedance: 50R
footprint Amphenol Connex (132366-10)
pins: 1, 2, 2, 2, 2

## SN74LV1T04DVBR_new
designator U?, comment SN74LV1T00DBVR
Übersetzungsspannungs-Pegel SGL PwrSupply 2-inpt Pos NAND gate; Manufacturer: TI
footprint SOT-23-5
pins: 1 NC, 2 A (in), 3 GND (power), 4 Y (out), 5 VCC (power)

## solder_jumper_closed
designator J?, comment closed 0R  (net tie)
0R; Manufacturer: Multicomp; Manufacturer Part Number: MC00625W040210R
footprint JP2_SMD_closed
pins: 1, 2

## solder_jumper_closed_0402
designator J?, comment closed 0R  (net tie)
0R; Manufacturer: Multicomp; Manufacturer Part Number: MC00625W040210R
footprint JP2_SMD_closed_0402
pins: 1, 2

## solder_jumper_open
designator J?, comment open  (no BOM)
footprint JP2_SMD_open
pins: 1, 2

## solder_jumper_open_0402
designator J?, comment open  (net tie, no BOM)
footprint JP2_SMD_open_0402
pins: 1, 2

## Spacer
designator P?
Samtec; Manufacturer: 3M; Manufacturer Part Number: SJ5303TRANS; 2nd Source: doublesourcing allowed
footprint spacer (spacer d5mmx4mm)

## Spacer_1
designator P?, comment Spacer
Samtec; Manufacturer: 3M; Manufacturer Part Number: SJ5303TRANS; 2nd Source: doublesourcing allowed
footprint SPACER_NEW (spacer d5mmx4mm)

## Spacer_2
designator P?, comment Spacer
Samtec; Manufacturer: 3M; Manufacturer Part Number: SJ5303TRANS; 2nd Source: doublesourcing allowed
footprint SPACER_NEW (spacer d5mmx4mm)

## SSW-105-02-G-S-RA
designator J?, comment Female Single Row Horizontal  (value not drawn)
Female Single Row Horizontal 5 pin; Manufacturer: Samtec; Manufacturer Part Number: SSW-105-02-G-S-RA; 2nd Source: doublesourcing allowed
footprint SSW-105-02-G-S-RA (5 Pin header 90deg)
pins: 1, 2, 3, 4, 5

## SSW-114-02-G-S-RA
designator J?, comment Female Single Row Horizontal  (value not drawn)
Female Single Row Horizontal 14 pin; Manufacturer: Samtec; Manufacturer Part Number: SSW-114-02-G-S-RA; 2nd Source: doublesourcing allowed
footprint SSW-114-02-G-S-RA (14 Pin header 90deg)
pins: 1, 2, 3, 4, 5, 6, 7, 8, 9, 10, 11, 12, 13, 14

## ST25R200
designator U200
HF Reader IC; Manufacturer: STMicroelectronics; Manufacturer Part Number: ST25R3916-AQFMCT-ND
footprint ST25R200 QFN (QFN, 24-Leads, Body 4.00x4.00mm, Pitch 0.50mm, Thermal Pad 2.65x2.65mm, IPC Medium Density)
pins: 1 IRQ, 2 MISO, 3 VDD_IO, 4 GND_D, 5 VDD_D, 6 VDD_AM, 7 VDD, 8 VDD_DR, 9 RFO1, 10 RFO2, 11 GND_DR, 12 TDA2, 13 TAD1, 14 VDD_A, 15 AGD, 16 RFI1, 17 RFI2, 18 GND_A, 19 XTI, 20 XTO, 21 RESET, 22 BSS, 23 MOSI, 24 SCLK, 25 VSS (power)

## ST25R210_QFN28
designator U200, comment ST25R210
HF Reader IC QFN28; Manufacturer: STMicroelectronics
footprint ST25R210_QFN_28 (QFN, 28-Leads, Body 3,95x3,95mm, Pitch 0,40mm, Thermal Pad 2,50x2,50mm, IPC Medium Density)
pins: 1 IRQ, 2 MISO, 3 VDD_IO, 4 GND_D, 5 VDD_D, 6 CE_SW1, 7 GND_SW, 8 CE SW2, 9 TAD1, 10 TAD2, 11 VDD, 12 RFO1, 13 GND_DR, 14 RFO2, 15 VDD_DR, 16 VDD_TX, 17 VDD_A, 18 RFI1, 19 RFI2, 20 AGD, 21 GND_A, 22 XTI, 23 XTO, 24 VSS, 25 RESET, 26 BSS, 27 MOSI, 28 SCLK, 29 GND

## ST25R300_QFN32
designator U?, comment ST25R300
HF Reader IC QFN32; Manufacturer: ST
footprint ST25R300-QFN32_5X5_0.5 (Footprint not found)
pins: 1 IRQ, 2 MISO, 3 VDD_IO, 4 GND_D, 5 VDD_D, 6 CE_GPIO1, 7 GND_GPIO, 8 NC GND, 9 CE_GPIO2, 10 NC GND, 11 TAD1, 12 TAD2, 13 VDD, 14 RFO1, 15 GND_DR, 16 RFO2, 17 NC GND, 18 VDD_DR, 19 VDD_TX, 20 VDD_A, 21 RFI1, 22 RFI2, 23 AGD, 24 NC GND, 25 GND_A, 26 XTI, 27 XTO, 28 VSS, 29 RESET, 30 BSS, 31 MOSI, 32 SCLK, 33 VSS (E.P.)

## ST25R500_QFN28
designator U200, comment ST25R500
HF Reader IC QFN28; Manufacturer: STMicroelectronics; Manufacturer Part Number: ST25R3916-AQFMCT-ND
footprint ST25R3916-QFN32_5X5_0.5
pins: 1 IRQ, 2 MISO, 3 VDD_IO, 4 GND_D, 5 VDD_D, 6 CE_SW1, 7 GND_SW, 8 CE_SW2, 9 TAD1, 10 TAD2, 11 VDD, 12 RFO1, 13 GND_DR, 14 RFO2, 15 VDD_DR, 16 VDD_TX, 17 VDD_A, 18 AGD, 19 RFI1, 20 RFI2, 21 GND_A, 22 XTI, 23 XTO, 24 VSS, 25 RESET, 26 BSS, 27 MOSI, 28 SCLK

## ST25R500_QFN32
designator U?, comment ST25R500
HF Reader IC QFN32; Manufacturer: STMicroelectronics; Manufacturer Part Number: ST25R3916-AQFMCT-ND
footprint ST25R3916-QFN32_5X5_0.5
pins: 1 IRQ, 2 MISO, 3 VDD_IO, 4 GND_D, 5 VDD_D, 6 CE_SW1, 7 GND_SW, 8 NC GND, 9 CE_SW2, 10 NC GND, 11 TAD1, 12 TAD2, 13 VDD, 14 RFO1, 15 GND_DR, 16 RFO2, 17 NC GND, 18 VDD_DR, 19 VDD_TX, 20 VDD_A, 21 RFI1, 22 RFI2, 23 AGD, 24 NC GND, 25 GND_A, 26 XTI, 27 XTO, 28 VSS, 29 RESET, 30 BSS, 31 MOSI, 32 SCLK, 33 VSS (E.P.)

## ST25R501_QFN24
designator U200, comment ST25R501
HF Reader IC QFN24; Manufacturer: STMicroelectronics; Manufacturer Part Number: ST25R3916-AQFMCT-ND
footprint ST25R200 QFN (QFN, 24-Leads, Body 4.00x4.00mm, Pitch 0.50mm, Thermal Pad 2.65x2.65mm, IPC Medium Density)
pins: 1 SCLK, 2 IRQ, 3 MISO, 4 VDD_IO, 5 GND_D, 6 VDD_D, 7 TAD1, 8 TAD2, 9 VDD, 10 RFO1, 11 GND_DR, 12 RFO2, 13 VDD_DR, 14 VDD_TX, 15 VDD_A, 16 RFI1, 17 RFI2, 18 AGD, 19 GND_A, 20 XTI, 21 XTO, 22 RESET, 23 BSS, 24 MOSI, 25 VSS (power)

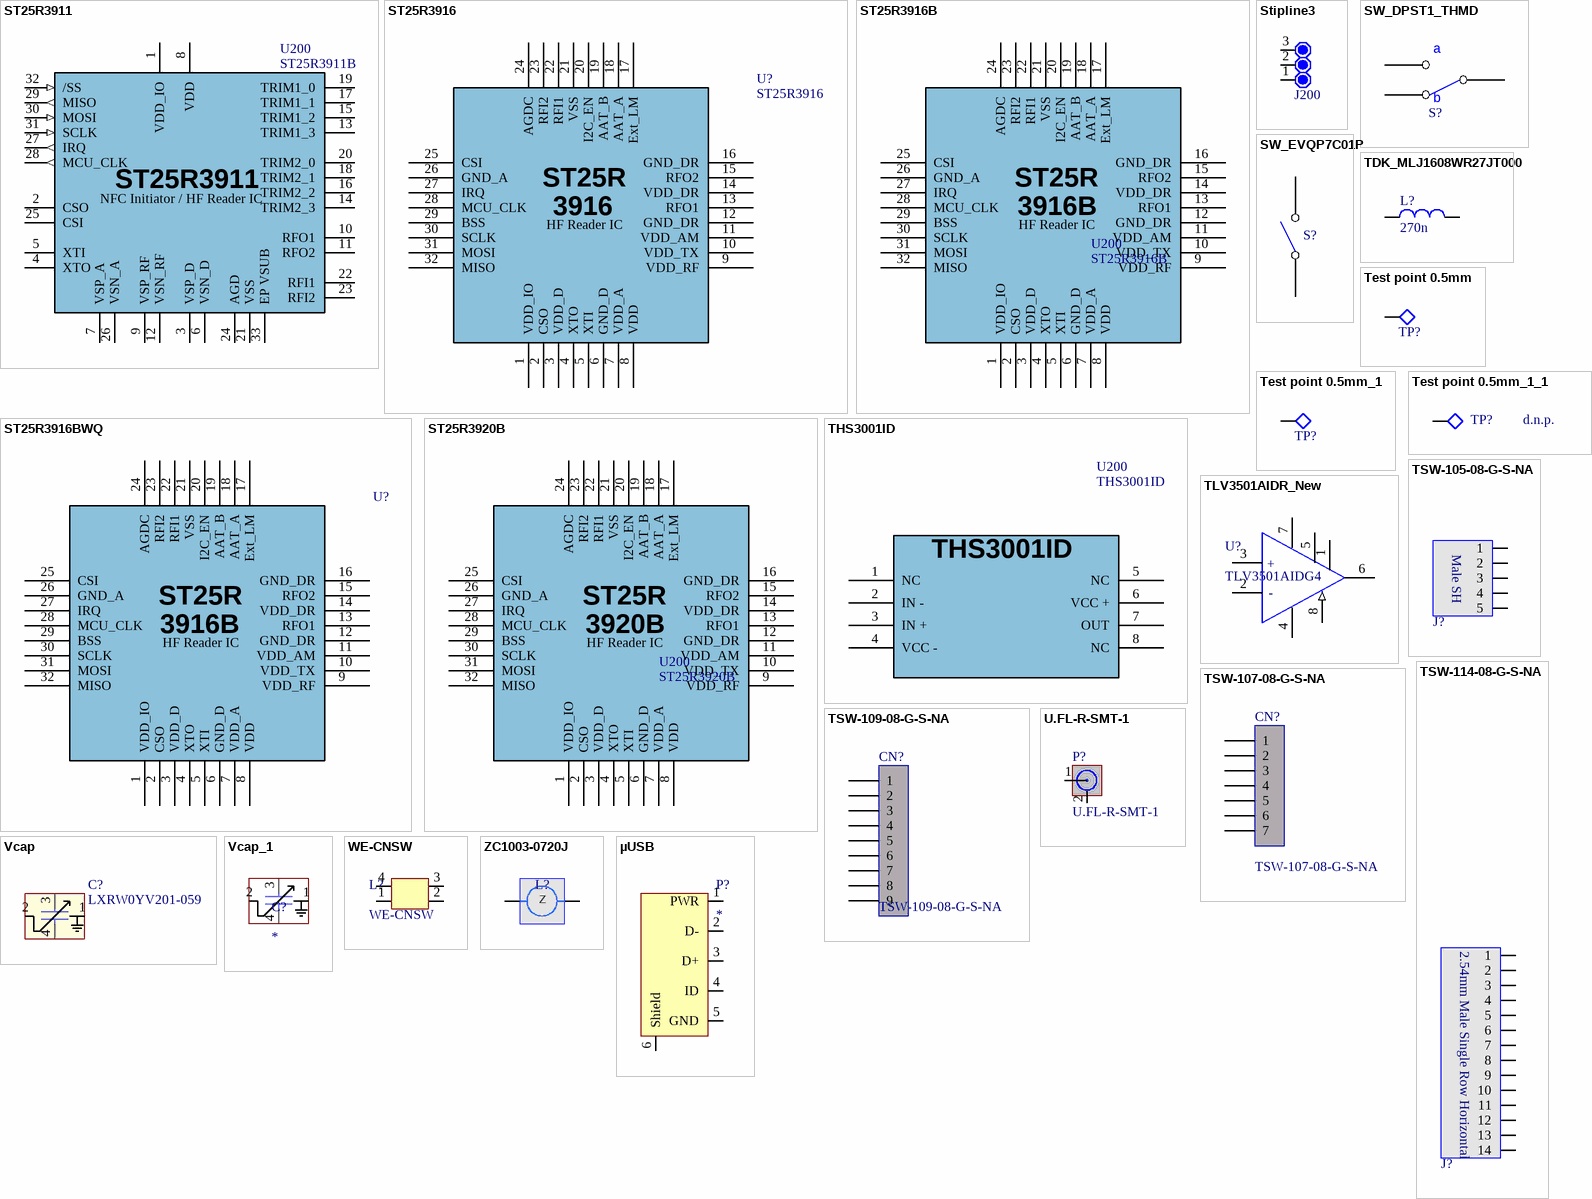
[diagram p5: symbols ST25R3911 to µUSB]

## ST25R3911
designator U200, comment ST25R3911B
NFC Initiator / HF Reader IC; Manufacturer: STMicroelectronics; Manufacturer Part Number: ST25R3911B-AQFMCT-ND
footprint ST25R3911B-QFN32_5X5_0.5
pins: 1 VDD_IO (power), 2 CSO, 3 VSP_D, 4 XTO, 5 XTI, 6 VSN_D (power), 7 VSP_A, 8 VDD (power), 9 VSP_RF, 10 RFO1, 11 RFO2, 12 VSN_RF (power), 13 TRIM1_3, 14 TRIM2_3, 15 TRIM1_2, 16 TRIM2_2, 17 TRIM1_1, 18 TRIM2_1, 19 TRIM1_0, 20 TRIM2_0, 21 VSS (power), 22 RFI1, 23 RFI2, 24 AGD, 25 CSI, 26 VSN_A (power), 27 IRQ (out), 28 MCU_CLK (out), 29 MISO (out), 30 MOSI (in), 31 SCLK (in), 32 /SS (in), 33 EP VSUB

## ST25R3916
designator U?
NFC Initiator / HF Reader IC; Manufacturer: STMicroelectronics; Manufacturer Part Number: ST25R3916-AQFMCT-ND
footprint ST25R3916-QFN32_5X5_0.5
pins: 1 VDD_IO, 2 CSO, 3 VDD_D, 4 XTO, 5 XTI, 6 GND_D, 7 VDD_A, 8 VDD, 9 VDD_RF, 10 VDD_TX, 11 VDD_AM, 12 GND_DR, 13 RFO1, 14 VDD_DR, 15 RFO2, 16 GND_DR, 17 Ext_LM, 18 AAT_A, 19 AAT_B, 20 I2C_EN, 21 VSS, 22 RFI1, 23 RFI2, 24 AGDC, 25 CSI, 26 GND_A, 27 IRQ, 28 MCU_CLK, 29 BSS, 30 SCLK, 31 MOSI, 32 MISO, 33 VSS (power)

## ST25R3916B
designator U200
NFC Initiator / HF Reader IC; Manufacturer: STMicroelectronics; Manufacturer Part Number: ST25R3916-AQFMCT-ND
footprint ST25R3916-QFN32_5X5_0.5
pins: 1 VDD_IO, 2 CSO, 3 VDD_D, 4 XTO, 5 XTI, 6 GND_D, 7 VDD_A, 8 VDD, 9 VDD_RF, 10 VDD_TX, 11 VDD_AM, 12 GND_DR, 13 RFO1, 14 VDD_DR, 15 RFO2, 16 GND_DR, 17 Ext_LM, 18 AAT_A, 19 AAT_B, 20 I2C_EN, 21 VSS, 22 RFI1, 23 RFI2, 24 AGDC, 25 CSI, 26 GND_A, 27 IRQ, 28 MCU_CLK, 29 BSS, 30 SCLK, 31 MOSI, 32 MISO, 33 VSS (power)

## ST25R3916BWQ
designator U?, comment ST25R3916B  (value not drawn)
NFC Initiator / HF Reader IC; Manufacturer: STMicroelectronics; Manufacturer Part Number: ST25R3916-BQW
footprint ST25R3916-QFN32_5X5_0.5
pins: 1 VDD_IO, 2 CSO, 3 VDD_D, 4 XTO, 5 XTI, 6 GND_D, 7 VDD_A, 8 VDD, 9 VDD_RF, 10 VDD_TX, 11 VDD_AM, 12 GND_DR, 13 RFO1, 14 VDD_DR, 15 RFO2, 16 GND_DR, 17 Ext_LM, 18 AAT_A, 19 AAT_B, 20 I2C_EN, 21 VSS, 22 RFI1, 23 RFI2, 24 AGDC, 25 CSI, 26 GND_A, 27 IRQ, 28 MCU_CLK, 29 BSS, 30 SCLK, 31 MOSI, 32 MISO, 33 VSS (power)

## ST25R3920B
designator U200
NFC Initiator / HF Reader IC; Manufacturer: STMicroelectronics; Manufacturer Part Number: ST25R3920B-AQWT
footprint ST25R3916-QFN32_5X5_0.5
pins: 1 VDD_IO, 2 CSO, 3 VDD_D, 4 XTO, 5 XTI, 6 GND_D, 7 VDD_A, 8 VDD, 9 VDD_RF, 10 VDD_TX, 11 VDD_AM, 12 GND_DR, 13 RFO1, 14 VDD_DR, 15 RFO2, 16 GND_DR, 17 Ext_LM, 18 AAT_A, 19 AAT_B, 20 I2C_EN, 21 VSS, 22 RFI1, 23 RFI2, 24 AGDC, 25 CSI, 26 GND_A, 27 IRQ, 28 MCU_CLK, 29 BSS, 30 SCLK, 31 MOSI, 32 MISO, 33 VSS (power)

## Stipline3
designator J200  (value not drawn)
footprint JP3_SMD
pins: 1, 2, 3

## SW_DPST1_THMD
designator S?, comment PCM12SMTR  (value not drawn)
Manufacturer: C & K COMPONENTS
footprint SW_PCM12SMTR
3D model Switch_slide_pcm12smtr (PCB3D Model)
pins: 1, 2, 3

## SW_EVQP7C01P
designator S?, comment EVQP7C01P  (value not drawn)
Manufacturer: Panasonic
footprint SW_EVQP7C01P
3D model Switch_slide_pcm12smtr (PCB3D Model)
pins: 1, 2

## TDK_MLJ1608WR27JT000
designator L?, comment 270n
MLJ1608WR27JT000; Manufacturer: TDK; 2nd Source: 0.27 uH 5 % 0.55A 0603
footprint L0603
pins: 1, 2

## Test point 0.5mm
designator TP?  (value not drawn)  (no BOM)
Part Number: Test point 0.5mm
footprint TP_0.5 (Test Point 0.5mm)
pins: 1 0

## Test point 0.5mm_1
designator TP?, comment d.n.p.  (value not drawn)  (no BOM)
Part Number: Test point 0.5mm
footprint 1*1P_MALE
pins: 1 0

## Test point 0.5mm_1_1
designator TP?, comment d.n.p.  (no BOM)
Part Number: Test point 0.5mm
footprint TP_0.5 (Test Point 0.5mm)
footprint 1*1P_MALE round
footprint TP_1mm
pins: 1 0

## THS3001ID
designator U200
footprint THS3001ID SOIC (D) (SOIC, 8-Leads, Body 3,90x3,90mm, Pitch 1,27mm, IPC Medium Density)
pins: 1 NC, 2 IN -, 3 IN +, 4 VCC -, 5 NC, 6 VCC +, 7 OUT, 8 NC

## TLV3501AIDR_New
designator U?, comment TLV3501AIDG4
Analoger Komparator, Rail-to-Rail, High-Speed-Komparator, 1 Komparator, 4.5 ns, 2.7V bis 5.5V, SOIC; Manufacturer: TI; Manufacturer Part Number: TLV3501AIDG4 .
footprint TLV3501-SOIC 8-Pin
pins: 1 NC (power), 2 -IN (hiz), 3 +IN (hiz), 4 V- (power), 5 NC (power), 6 OUT, 7 V+ (power), 8 SHDN (in)

## TSW-105-08-G-S-NA
designator J?, comment Male Single Row Horizontal  (value not drawn)
Male Single Row Horizontal 5 pin; Manufacturer: Samtec; Manufacturer Part Number: TSW-105-08-G-S-NA; 2nd Source: doublesourcing allowed
footprint TSW-105-08-G-S-NA (5 Pin header 90deg)
pins: 1, 2, 3, 4, 5

## TSW-107-08-G-S-NA
designator CN?
Manufacturer: Samtec; Comments: RECEPTACLE, 2.54MM, SINGLE ROW, 7WAY; 2nd source: doublesourcing allowed
footprint TSW-107-08-G-S-NA
pins: 1, 2, 3, 4, 5, 6, 7

## TSW-109-08-G-S-NA
designator CN?
Manufacturer: Samtec; Comments: RECEPTACLE, 2.54MM, SINGLE ROW, 7WAY; 2nd source: doublesourcing allowed
footprint TSW-109-08-G-S-NA
pins: 1, 2, 3, 4, 5, 6, 7, 8, 9

## TSW-114-08-G-S-NA
designator J?, comment Male Single Row Horizontal  (value not drawn)
Male Single Row Horizontal 14 pin; Manufacturer: Samtec; Manufacturer Part Number: TSW-114-08-G-S-NA; 2nd Source: doublesourcing allowed
footprint TSW-114-08-G-S-NA (14 Pin header 90deg)
pins: 1, 2, 3, 4, 5, 6, 7, 8, 9, 10, 11, 12, 13, 14

## U.FL-R-SMT-1
designator P?
Manufacturer: HIROSE(HRS); Manufacturer Part Number: U.FL-R-SMT-1(10); 2nd Source: yes
footprint U FL Socket - HRS - Surface Mount
pins: 1, 2, 3

## Vcap
designator C?, comment LXRW0YV201-059
Manufacturer: muRata
footprint Vcap_csp_combo
pins: 1, 2, 3, 4

## Vcap_1
designator C?
Manufacturer: muRata; Manufacturer Part Number: LXRW0YV900-053
footprint Vcap_csp_combo
pins: 1, 2, 3, 4

## WE-CNSW
designator L?
footprint CNSW_744230900
pins: 1, 2, 3, 4

## ZC1003-0720J
designator L?, comment Premo Vertical Single Axis 125kHz coil  (value not drawn)
footprint ZC1003 (Premo 125kHz Vertical Transponder Antenna)
pins: 0, 1

## µUSB
designator P?
Manufacturer: Molex; Manufacturer Part Number: 105017-0001
footprint µUSB Molex (105017)
pins: 1 PWR, 2 D-, 3 D+, 4 ID, 5 GND, 6 Shield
